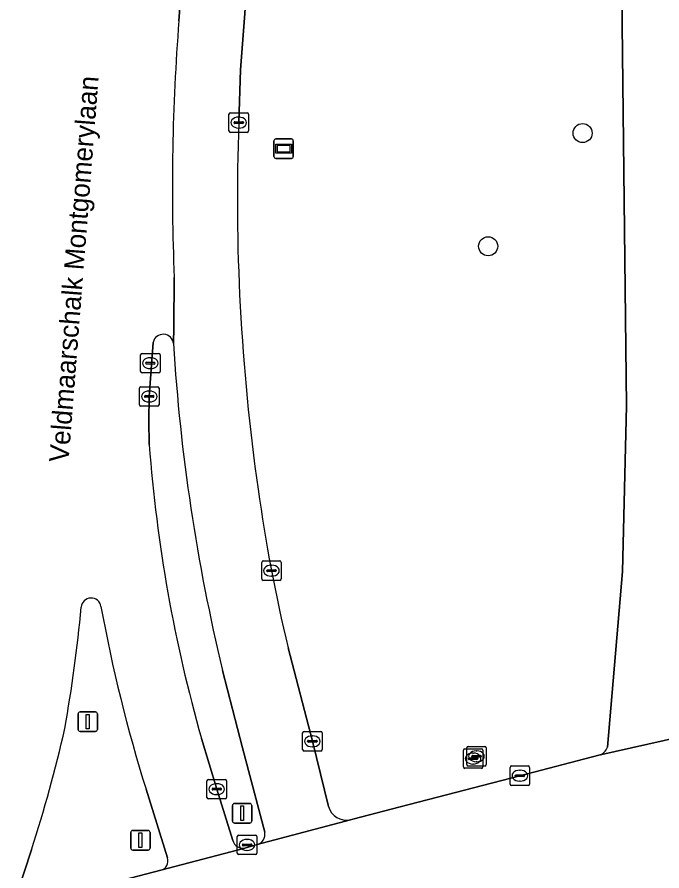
# Model space of a CAD drawing. Extents: x 160806 to 161707, y 383696 to 384148.
# Drawn here: x 161203.78 to 161236.82, y 383930.02 to 383973.77 of the extents above; entities that cross this region are included whole.
import ezdxf

# ---------------------------------------------------------------- set-up
doc = ezdxf.new("R2010")
doc.units = 0
for name, color, linetype in [('IMGEO_Berm_groen', 7, 'Continuous'), ('IMGEO_Boom', 7, 'Continuous'), ('IMGEO_Kolk', 7, 'Continuous'), ('IMGEO_Openbare_ruimte_label', 7, 'Continuous'), ('IMGEO_OVBaan_gesloten', 7, 'Continuous'), ('IMGEO_Rijbaan_lokaal_gesloten', 7, 'Continuous'), ('IMGEO_Rioolput', 7, 'Continuous'), ('IMGEO_Verkeerseiland_gesloten', 7, 'Continuous'), ('IMGEO_Verkeersregelinstallatiepaal', 7, 'Continuous'), ('IMGEO_Wegwijzer', 7, 'Continuous')]:
    doc.layers.add(name, color=color, linetype=linetype)

msp = doc.modelspace()

# ---------------------------------------------------------------- linework, layer by layer
at = {"layer": 'IMGEO_Berm_groen'}
for points in [[(161234.023, 383936.363), (161234.793, 383945.355), (161235.013, 383953.847), (161234.492, 383998.945), (161234.263, 384024.171)], [(161217.59, 384002.154), (161216.53, 383988.019), (161215.222, 383971.062), (161215.137, 383968.364)], [(161217.663, 383941.452), (161218.909, 383936.658), (161219.729, 383933.32)], [(161220.861, 383932.636), (161220.976, 383932.667), (161223.402, 383933.299), (161229.542, 383934.895), (161233.595, 383935.943)]]:
    msp.add_lwpolyline(points, dxfattribs=at)
for centre, radius, start, end in [((161320.498, 383964.509), 105.432, 177.9047, 188.14488), ((161299.612, 383961.128), 84.278, 187.88118, 193.50125), ((161233.438, 383936.531), 0.609, 284.9675, 343.9515), ((161220.669, 383933.597), 0.98, 196.3992, 281.3167)]:
    msp.add_arc(centre, radius, start, end, dxfattribs=at)
at = {"layer": 'IMGEO_Boom'}
for centre in [(161232.756, 383967.827), (161227.918, 383962.027)]:
    msp.add_circle(centre, 0.489, dxfattribs=at)
at = {"layer": 'IMGEO_Kolk'}
for p, q in [((161214.636, 383967.938), (161214.636, 383968.79)), ((161214.711, 383968.864), (161215.563, 383968.864)), ((161215.124, 383968.644), (161215.149, 383968.644)), ((161215.637, 383968.79), (161215.637, 383967.938)), ((161214.895, 383968.358), (161214.895, 383968.37)), ((161215.333, 383968.321), (161214.935, 383968.321)), ((161214.938, 383968.407), (161215.336, 383968.407)), ((161215.147, 383968.084), (161215.122, 383968.084)), ((161215.379, 383968.37), (161215.379, 383968.358)), ((161215.563, 383967.864), (161214.711, 383967.864)), ((161210.106, 383955.61), (161210.106, 383956.462)), ((161210.181, 383956.536), (161211.033, 383956.536)), ((161210.594, 383956.316), (161210.619, 383956.316)), ((161211.107, 383956.462), (161211.107, 383955.61)), ((161210.365, 383956.03), (161210.365, 383956.042)), ((161210.803, 383955.993), (161210.405, 383955.993)), ((161210.408, 383956.079), (161210.806, 383956.079)), ((161210.849, 383956.042), (161210.849, 383956.03)), ((161211.033, 383955.536), (161210.181, 383955.536)), ((161210.617, 383955.756), (161210.592, 383955.756)), ((161210.051, 383953.904), (161210.051, 383954.756)), ((161210.126, 383954.83), (161210.978, 383954.83)), ((161210.539, 383954.61), (161210.564, 383954.61)), ((161211.052, 383954.756), (161211.052, 383953.904)), ((161210.31, 383954.324), (161210.31, 383954.336)), ((161210.748, 383954.287), (161210.35, 383954.287)), ((161210.353, 383954.373), (161210.751, 383954.373)), ((161210.794, 383954.336), (161210.794, 383954.324)), ((161210.978, 383953.83), (161210.126, 383953.83)), ((161210.562, 383954.05), (161210.537, 383954.05)), ((161216.313, 383944.977), (161216.313, 383945.829)), ((161216.388, 383945.903), (161217.24, 383945.903)), ((161217.314, 383945.829), (161217.314, 383944.977)), ((161216.572, 383945.397), (161216.572, 383945.409)), ((161217.01, 383945.36), (161216.612, 383945.36)), ((161216.615, 383945.446), (161217.013, 383945.446)), ((161216.801, 383945.683), (161216.826, 383945.683)), ((161217.056, 383945.409), (161217.056, 383945.397)), ((161217.24, 383944.903), (161216.388, 383944.903)), ((161216.824, 383945.123), (161216.799, 383945.123)), ((161218.408, 383936.232), (161218.408, 383937.084)), ((161218.483, 383937.158), (161219.335, 383937.158)), ((161219.409, 383937.084), (161219.409, 383936.232)), ((161218.667, 383936.652), (161218.667, 383936.664)), ((161219.105, 383936.615), (161218.707, 383936.615)), ((161218.71, 383936.701), (161219.108, 383936.701)), ((161218.896, 383936.938), (161218.921, 383936.938)), ((161219.151, 383936.664), (161219.151, 383936.652)), ((161219.335, 383936.158), (161218.483, 383936.158)), ((161218.919, 383936.378), (161218.894, 383936.378)), ((161229.041, 383934.469), (161229.041, 383935.321)), ((161229.116, 383935.395), (161229.968, 383935.395)), ((161230.042, 383935.321), (161230.042, 383934.469)), ((161229.3, 383934.889), (161229.3, 383934.901)), ((161229.738, 383934.852), (161229.34, 383934.852)), ((161229.343, 383934.938), (161229.741, 383934.938)), ((161229.529, 383935.175), (161229.554, 383935.175)), ((161229.784, 383934.901), (161229.784, 383934.889)), ((161213.508, 383933.781), (161213.508, 383934.633)), ((161213.583, 383934.707), (161214.435, 383934.707)), ((161213.996, 383934.487), (161214.021, 383934.487)), ((161214.509, 383934.633), (161214.509, 383933.781)), ((161229.968, 383934.395), (161229.116, 383934.395)), ((161229.552, 383934.615), (161229.527, 383934.615)), ((161213.767, 383934.201), (161213.767, 383934.213)), ((161214.205, 383934.164), (161213.807, 383934.164)), ((161213.81, 383934.25), (161214.208, 383934.25)), ((161214.251, 383934.213), (161214.251, 383934.201)), ((161214.435, 383933.707), (161213.583, 383933.707)), ((161214.019, 383933.927), (161213.994, 383933.927)), ((161215.062, 383930.923), (161215.062, 383931.775)), ((161215.137, 383931.849), (161215.989, 383931.849)), ((161216.063, 383931.775), (161216.063, 383930.923)), ((161215.321, 383931.343), (161215.321, 383931.355)), ((161215.364, 383931.392), (161215.762, 383931.392)), ((161215.55, 383931.629), (161215.575, 383931.629)), ((161215.805, 383931.355), (161215.805, 383931.343)), ((161215.759, 383931.306), (161215.361, 383931.306)), ((161215.573, 383931.069), (161215.548, 383931.069)), ((161215.989, 383930.849), (161215.137, 383930.849))]:
    msp.add_line(p, q, dxfattribs=at)
for points in [[(161214.636, 383967.938), (161214.636, 383968.79)], [(161214.711, 383968.864), (161215.563, 383968.864)], [(161215.637, 383968.79), (161215.637, 383967.938)], [(161215.563, 383967.864), (161214.711, 383967.864)], [(161210.106, 383955.61), (161210.106, 383956.462)], [(161210.181, 383956.536), (161211.033, 383956.536)], [(161211.107, 383956.462), (161211.107, 383955.61)], [(161211.033, 383955.536), (161210.181, 383955.536)], [(161210.051, 383953.904), (161210.051, 383954.756)], [(161210.126, 383954.83), (161210.978, 383954.83)], [(161211.052, 383954.756), (161211.052, 383953.904)], [(161210.978, 383953.83), (161210.126, 383953.83)], [(161216.313, 383944.977), (161216.313, 383945.829)], [(161216.388, 383945.903), (161217.24, 383945.903)], [(161217.314, 383945.829), (161217.314, 383944.977)], [(161217.24, 383944.903), (161216.388, 383944.903)], [(161218.408, 383936.232), (161218.408, 383937.084)], [(161218.483, 383937.158), (161219.335, 383937.158)], [(161219.409, 383937.084), (161219.409, 383936.232)], [(161219.335, 383936.158), (161218.483, 383936.158)], [(161229.041, 383934.469), (161229.041, 383935.321)], [(161229.116, 383935.395), (161229.968, 383935.395)], [(161230.042, 383935.321), (161230.042, 383934.469)], [(161213.508, 383933.781), (161213.508, 383934.633)], [(161213.583, 383934.707), (161214.435, 383934.707)], [(161214.509, 383934.633), (161214.509, 383933.781)], [(161229.968, 383934.395), (161229.116, 383934.395)], [(161214.435, 383933.707), (161213.583, 383933.707)], [(161215.062, 383930.923), (161215.062, 383931.775)], [(161215.137, 383931.849), (161215.989, 383931.849)], [(161216.063, 383931.775), (161216.063, 383930.923)], [(161215.989, 383930.849), (161215.137, 383930.849)]]:
    msp.add_lwpolyline(points, dxfattribs=at)
for centre, radius, start, end in [((161214.713, 383968.788), 0.0765, 91.552, 178.448), ((161214.713, 383968.788), 0.0765, 91.552, 178.448), ((161215.561, 383968.788), 0.0765, 1.552, 88.448), ((161215.561, 383968.788), 0.0765, 1.552, 88.448), ((161214.935, 383968.367), 0.0403, 85.8775, 175.7526), ((161214.932, 383968.357), 0.0366, 178.938, 274.7102), ((161215.336, 383968.364), 0.043, 264.8664, 352.4533), ((161215.34, 383968.369), 0.0386, 1.7309, 96.639), ((161214.713, 383967.94), 0.0765, 181.552, 268.448), ((161214.713, 383967.94), 0.0765, 181.552, 268.448), ((161215.561, 383967.94), 0.0765, 271.552, 358.448), ((161215.561, 383967.94), 0.0765, 271.552, 358.448), ((161210.183, 383956.46), 0.0765, 91.552, 178.448), ((161210.183, 383956.46), 0.0765, 91.552, 178.448), ((161211.031, 383956.46), 0.0765, 1.552, 88.448), ((161211.031, 383956.46), 0.0765, 1.552, 88.448), ((161210.405, 383956.039), 0.0403, 85.8775, 175.7526), ((161210.402, 383956.029), 0.0366, 178.938, 274.7102), ((161210.806, 383956.036), 0.043, 264.8664, 352.4533), ((161210.81, 383956.041), 0.0386, 1.7309, 96.639), ((161210.183, 383955.612), 0.0765, 181.552, 268.448), ((161210.183, 383955.612), 0.0765, 181.552, 268.448), ((161211.031, 383955.612), 0.0765, 271.552, 358.448), ((161211.031, 383955.612), 0.0765, 271.552, 358.448), ((161210.128, 383954.754), 0.0765, 91.552, 178.448), ((161210.128, 383954.754), 0.0765, 91.552, 178.448), ((161210.976, 383954.754), 0.0765, 1.552, 88.448), ((161210.976, 383954.754), 0.0765, 1.552, 88.448), ((161210.35, 383954.333), 0.0403, 85.8775, 175.7526), ((161210.347, 383954.323), 0.0366, 178.938, 274.7102), ((161210.751, 383954.33), 0.043, 264.8664, 352.4533), ((161210.755, 383954.335), 0.0386, 1.7309, 96.639), ((161210.128, 383953.906), 0.0765, 181.552, 268.448), ((161210.128, 383953.906), 0.0765, 181.552, 268.448), ((161210.976, 383953.906), 0.0765, 271.552, 358.448), ((161210.976, 383953.906), 0.0765, 271.552, 358.448), ((161216.39, 383945.827), 0.0765, 91.552, 178.448), ((161216.39, 383945.827), 0.0765, 91.552, 178.448), ((161217.238, 383945.827), 0.0765, 1.552, 88.448), ((161217.238, 383945.827), 0.0765, 1.552, 88.448), ((161216.612, 383945.406), 0.0403, 85.8775, 175.7526), ((161216.609, 383945.396), 0.0366, 178.938, 274.7102), ((161217.013, 383945.403), 0.043, 264.8664, 352.4533), ((161217.017, 383945.408), 0.0386, 1.7309, 96.639), ((161216.39, 383944.979), 0.0765, 181.552, 268.448), ((161216.39, 383944.979), 0.0765, 181.552, 268.448), ((161217.238, 383944.979), 0.0765, 271.552, 358.448), ((161217.238, 383944.979), 0.0765, 271.552, 358.448), ((161218.485, 383937.082), 0.0765, 91.552, 178.448), ((161218.485, 383937.082), 0.0765, 91.552, 178.448), ((161219.333, 383937.082), 0.0765, 1.552, 88.448), ((161219.333, 383937.082), 0.0765, 1.552, 88.448), ((161218.707, 383936.661), 0.0403, 85.8775, 175.7526), ((161218.704, 383936.651), 0.0366, 178.938, 274.7102), ((161219.108, 383936.658), 0.043, 264.8664, 352.4533), ((161219.112, 383936.663), 0.0386, 1.7309, 96.639), ((161218.485, 383936.234), 0.0765, 181.552, 268.448), ((161218.485, 383936.234), 0.0765, 181.552, 268.448), ((161219.333, 383936.234), 0.0765, 271.552, 358.448), ((161219.333, 383936.234), 0.0765, 271.552, 358.448), ((161229.118, 383935.319), 0.0765, 91.552, 178.448), ((161229.118, 383935.319), 0.0765, 91.552, 178.448), ((161229.966, 383935.319), 0.0765, 1.552, 88.448), ((161229.966, 383935.319), 0.0765, 1.552, 88.448), ((161229.34, 383934.898), 0.0403, 85.8775, 175.7526), ((161229.337, 383934.888), 0.0366, 178.938, 274.7102), ((161229.741, 383934.895), 0.043, 264.8664, 352.4533), ((161229.745, 383934.9), 0.0386, 1.7309, 96.639), ((161213.585, 383934.631), 0.0765, 91.552, 178.448), ((161213.585, 383934.631), 0.0765, 91.552, 178.448), ((161214.433, 383934.631), 0.0765, 1.552, 88.448), ((161214.433, 383934.631), 0.0765, 1.552, 88.448), ((161229.118, 383934.471), 0.0765, 181.552, 268.448), ((161229.118, 383934.471), 0.0765, 181.552, 268.448), ((161229.966, 383934.471), 0.0765, 271.552, 358.448), ((161229.966, 383934.471), 0.0765, 271.552, 358.448), ((161213.807, 383934.21), 0.0403, 85.8775, 175.7526), ((161213.804, 383934.2), 0.0366, 178.938, 274.7102), ((161214.208, 383934.207), 0.043, 264.8664, 352.4533), ((161214.212, 383934.212), 0.0386, 1.7309, 96.639), ((161213.585, 383933.783), 0.0765, 181.552, 268.448), ((161213.585, 383933.783), 0.0765, 181.552, 268.448), ((161214.433, 383933.783), 0.0765, 271.552, 358.448), ((161214.433, 383933.783), 0.0765, 271.552, 358.448), ((161215.139, 383931.773), 0.0765, 91.552, 178.448), ((161215.139, 383931.773), 0.0765, 91.552, 178.448), ((161215.987, 383931.773), 0.0765, 1.552, 88.448), ((161215.987, 383931.773), 0.0765, 1.552, 88.448), ((161215.361, 383931.352), 0.0403, 85.8775, 175.7526), ((161215.358, 383931.342), 0.0366, 178.938, 274.7102), ((161215.762, 383931.349), 0.043, 264.8664, 352.4533), ((161215.766, 383931.354), 0.0386, 1.7309, 96.639), ((161215.139, 383930.925), 0.0765, 181.552, 268.448), ((161215.139, 383930.925), 0.0765, 181.552, 268.448), ((161215.987, 383930.925), 0.0765, 271.552, 358.448), ((161215.987, 383930.925), 0.0765, 271.552, 358.448)]:
    msp.add_arc(centre, radius, start, end, dxfattribs=at)
for centre, major_axis, ratio, start_param, end_param in [((161215.123, 383968.364), (-0.387, 0.002), 0.722429, 4.712389, 7.853982), ((161215.148, 383968.364), (-0.39, 0.002), 0.717154, 1.570796, 4.712389), ((161210.593, 383956.036), (-0.387, 0.002), 0.722429, 4.712389, 7.853982), ((161210.618, 383956.036), (-0.39, 0.002), 0.717154, 1.570796, 4.712389), ((161210.538, 383954.33), (-0.387, 0.002), 0.722429, 4.712389, 7.853982), ((161210.563, 383954.33), (-0.39, 0.002), 0.717154, 1.570796, 4.712389), ((161216.8, 383945.403), (-0.387, 0.002), 0.722429, 4.712389, 7.853982), ((161216.825, 383945.403), (-0.39, 0.002), 0.717154, 1.570796, 4.712389), ((161218.895, 383936.658), (-0.387, 0.002), 0.722429, 4.712389, 7.853982), ((161218.92, 383936.658), (-0.39, 0.002), 0.717154, 1.570796, 4.712389), ((161229.528, 383934.895), (-0.387, 0.002), 0.722429, 4.712389, 7.853982), ((161229.553, 383934.895), (-0.39, 0.002), 0.717154, 1.570796, 4.712389), ((161213.995, 383934.207), (-0.387, 0.002), 0.722429, 4.712389, 7.853982), ((161214.02, 383934.207), (-0.39, 0.002), 0.717154, 1.570796, 4.712389), ((161215.549, 383931.349), (-0.387, 0.002), 0.722429, 4.712389, 7.853982), ((161215.574, 383931.349), (-0.39, 0.002), 0.717154, 1.570796, 4.712389)]:
    msp.add_ellipse(centre, major_axis=major_axis, ratio=ratio, start_param=start_param, end_param=end_param, dxfattribs=at)
at = {"layer": 'IMGEO_OVBaan_gesloten'}
for points in [[(161214.441, 384004.323), (161212.071, 383973.586)], [(161215.137, 383968.364), (161215.222, 383971.062), (161216.53, 383988.019), (161217.59, 384002.154)], [(161211.83, 383960.427), (161211.811, 383957.889), (161211.793, 383957.036)], [(161219.729, 383933.32), (161218.909, 383936.658), (161217.663, 383941.452)], [(161214.31, 383940.287), (161215.337, 383936.331), (161216.466, 383931.999)], [(161216.084, 383931.37), (161220.861, 383932.636)]]:
    msp.add_lwpolyline(points, dxfattribs=at)
for centre, radius, start, end in [((161322.247, 383964.986), 110.511, 175.53696, 182.36459), ((161320.498, 383964.509), 105.432, 177.9047, 188.14488), ((161307.986, 383962.928), 96.373, 183.50511, 193.58753), ((161299.612, 383961.128), 84.278, 187.88118, 193.50125), ((161220.669, 383933.597), 0.98, 196.3992, 281.3167), ((161215.942, 383931.887), 0.536, 285.3781, 12.0801)]:
    msp.add_arc(centre, radius, start, end, dxfattribs=at)
at = {"layer": 'IMGEO_Rijbaan_lokaal_gesloten'}
for points in [[(161234.263, 384024.171), (161234.492, 383998.945), (161235.013, 383953.847), (161234.793, 383945.355), (161234.023, 383936.363)], [(161212.071, 383973.586), (161214.441, 384004.323)], [(161211.793, 383957.036), (161211.811, 383957.889), (161211.83, 383960.427)], [(161210.551, 383951.863), (161210.527, 383953.098), (161210.552, 383954.33), (161210.749, 383957.101)], [(161233.595, 383935.943), (161251.997, 383940.077), (161251.406, 383942.179)], [(161244.748, 383927.603), (161251.351, 383929.295), (161254.781, 383930.174), (161253.925, 383933.217), (161253.022, 383936.431), (161251.997, 383940.077), (161233.595, 383935.943), (161229.542, 383934.895), (161223.402, 383933.299), (161220.976, 383932.667), (161220.861, 383932.636), (161216.084, 383931.37), (161215.456, 383931.183), (161211.147, 383930.051), (161204.418, 383928.292)], [(161214.826, 383931.579), (161214.009, 383934.207), (161213.226, 383936.804)], [(161210.386, 383934.199), (161211.485, 383930.681)], [(161203.779, 383928.854), (161204.51, 383931.103)], [(161211.147, 383930.051), (161215.456, 383931.183)]]:
    msp.add_lwpolyline(points, dxfattribs=at)
for centre, radius, start, end in [((161322.247, 383964.986), 110.511, 175.53696, 182.36459), ((161211.266, 383956.986), 0.53, 5.4349, 167.4397), ((161286.07, 383957.511), 75.73, 184.27689, 195.86841), ((161207.572, 383943.487), 0.512, 9.1292, 174.7041), ((161132.556, 383950.401), 74.822, 349.92486, 354.73388), ((161286.065, 383957.811), 79.277, 190.34993, 197.32795), ((161140.112, 383952.221), 67.772, 341.84401, 347.29156), ((161233.438, 383936.531), 0.609, 284.9675, 343.9515), ((161215.357, 383931.724), 0.55, 195.3077, 280.3877), ((161211.017, 383930.527), 0.493, 285.3402, 18.232)]:
    msp.add_arc(centre, radius, start, end, dxfattribs=at)
at = {"layer": 'IMGEO_Rioolput'}
for p, q in [((161226.646, 383935.347), (161226.646, 383936.199)), ((161226.721, 383936.273), (161227.573, 383936.273)), ((161226.817, 383935.464), (161226.817, 383936.316)), ((161226.892, 383936.39), (161227.744, 383936.39)), ((161227.305, 383936.17), (161227.33, 383936.17)), ((161227.647, 383936.199), (161227.647, 383935.347)), ((161227.818, 383936.316), (161227.818, 383935.464)), ((161226.905, 383935.767), (161226.905, 383935.779)), ((161227.343, 383935.73), (161226.945, 383935.73)), ((161226.948, 383935.816), (161227.346, 383935.816)), ((161227.076, 383935.884), (161227.076, 383935.896)), ((161227.514, 383935.847), (161227.116, 383935.847)), ((161227.119, 383935.933), (161227.517, 383935.933)), ((161227.134, 383936.053), (161227.159, 383936.053)), ((161227.389, 383935.779), (161227.389, 383935.767)), ((161227.56, 383935.896), (161227.56, 383935.884)), ((161227.573, 383935.273), (161226.721, 383935.273)), ((161227.744, 383935.39), (161226.892, 383935.39)), ((161227.157, 383935.493), (161227.132, 383935.493)), ((161227.328, 383935.61), (161227.303, 383935.61))]:
    msp.add_line(p, q, dxfattribs=at)
for points in [[(161226.646, 383935.347), (161226.646, 383936.199)], [(161226.721, 383936.273), (161227.573, 383936.273)], [(161226.817, 383935.464), (161226.817, 383936.316)], [(161226.892, 383936.39), (161227.744, 383936.39)], [(161227.647, 383936.199), (161227.647, 383935.347)], [(161227.818, 383936.316), (161227.818, 383935.464)], [(161227.573, 383935.273), (161226.721, 383935.273)], [(161227.744, 383935.39), (161226.892, 383935.39)]]:
    msp.add_lwpolyline(points, dxfattribs=at)
for centre, radius, start, end in [((161226.723, 383936.197), 0.0765, 91.552, 178.448), ((161226.723, 383936.197), 0.0765, 91.552, 178.448), ((161226.894, 383936.314), 0.0765, 91.552, 178.448), ((161226.894, 383936.314), 0.0765, 91.552, 178.448), ((161227.571, 383936.197), 0.0765, 1.552, 88.448), ((161227.571, 383936.197), 0.0765, 1.552, 88.448), ((161227.742, 383936.314), 0.0765, 1.552, 88.448), ((161227.742, 383936.314), 0.0765, 1.552, 88.448), ((161226.945, 383935.776), 0.0403, 85.8775, 175.7526), ((161226.942, 383935.766), 0.0366, 178.938, 274.7102), ((161227.116, 383935.893), 0.0403, 85.8775, 175.7526), ((161227.113, 383935.883), 0.0366, 178.938, 274.7102), ((161227.346, 383935.773), 0.043, 264.8664, 352.4533), ((161227.35, 383935.778), 0.0386, 1.7309, 96.639), ((161227.517, 383935.89), 0.043, 264.8664, 352.4533), ((161227.521, 383935.895), 0.0386, 1.7309, 96.639), ((161226.723, 383935.349), 0.0765, 181.552, 268.448), ((161226.723, 383935.349), 0.0765, 181.552, 268.448), ((161226.894, 383935.466), 0.0765, 181.552, 268.448), ((161226.894, 383935.466), 0.0765, 181.552, 268.448), ((161227.571, 383935.349), 0.0765, 271.552, 358.448), ((161227.571, 383935.349), 0.0765, 271.552, 358.448), ((161227.742, 383935.466), 0.0765, 271.552, 358.448), ((161227.742, 383935.466), 0.0765, 271.552, 358.448)]:
    msp.add_arc(centre, radius, start, end, dxfattribs=at)
for centre, major_axis, ratio, start_param, end_param in [((161227.304, 383935.89), (-0.387, 0.002), 0.722429, 4.712389, 7.853982), ((161227.329, 383935.89), (-0.39, 0.002), 0.717154, 1.570796, 4.712389), ((161227.133, 383935.773), (-0.387, 0.002), 0.722429, 4.712389, 7.853982), ((161227.158, 383935.773), (-0.39, 0.002), 0.717154, 1.570796, 4.712389)]:
    msp.add_ellipse(centre, major_axis=major_axis, ratio=ratio, start_param=start_param, end_param=end_param, dxfattribs=at)
at = {"layer": 'IMGEO_Verkeerseiland_gesloten'}
for points in [[(161210.749, 383957.101), (161210.552, 383954.33), (161210.527, 383953.098), (161210.551, 383951.863)], [(161216.466, 383931.999), (161215.337, 383936.331), (161214.31, 383940.287)], [(161213.226, 383936.804), (161214.009, 383934.207), (161214.826, 383931.579)], [(161211.485, 383930.681), (161210.386, 383934.199)], [(161215.456, 383931.183), (161216.084, 383931.37)], [(161204.51, 383931.103), (161203.779, 383928.854)], [(161204.418, 383928.292), (161211.147, 383930.051)]]:
    msp.add_lwpolyline(points, dxfattribs=at)
for centre, radius, start, end in [((161211.266, 383956.986), 0.53, 5.4349, 167.4397), ((161307.986, 383962.928), 96.373, 183.50511, 193.58753), ((161286.07, 383957.511), 75.73, 184.27689, 195.86841), ((161207.572, 383943.487), 0.512, 9.1292, 174.7041), ((161132.556, 383950.401), 74.822, 349.92486, 354.73388), ((161286.065, 383957.811), 79.277, 190.34993, 197.32795), ((161140.112, 383952.221), 67.772, 341.84401, 347.29156), ((161215.942, 383931.887), 0.536, 285.3781, 12.0801), ((161215.357, 383931.724), 0.55, 195.3077, 280.3877), ((161211.017, 383930.527), 0.493, 285.3402, 18.232)]:
    msp.add_arc(centre, radius, start, end, dxfattribs=at)
at = {"layer": 'IMGEO_Verkeersregelinstallatiepaal'}
for p, q in [((161206.906, 383937.264), (161206.906, 383938.064)), ((161206.906, 383938.064), (161206.906, 383937.264)), ((161207.006, 383938.164), (161207.796, 383938.164)), ((161207.796, 383938.164), (161207.006, 383938.164)), ((161207.896, 383938.064), (161207.896, 383937.264)), ((161207.896, 383937.264), (161207.896, 383938.064)), ((161207.796, 383937.164), (161207.006, 383937.164)), ((161207.006, 383937.164), (161207.796, 383937.164)), ((161214.816, 383932.571), (161214.816, 383933.371)), ((161214.816, 383933.371), (161214.816, 383932.571)), ((161214.916, 383933.471), (161215.706, 383933.471)), ((161215.706, 383933.471), (161214.916, 383933.471)), ((161215.806, 383933.371), (161215.806, 383932.571)), ((161215.806, 383932.571), (161215.806, 383933.371)), ((161215.706, 383932.471), (161214.916, 383932.471)), ((161214.916, 383932.471), (161215.706, 383932.471)), ((161209.606, 383931.187), (161209.606, 383931.987)), ((161209.606, 383931.987), (161209.606, 383931.187)), ((161209.706, 383932.087), (161210.496, 383932.087)), ((161210.496, 383932.087), (161209.706, 383932.087)), ((161210.596, 383931.987), (161210.596, 383931.187)), ((161210.596, 383931.187), (161210.596, 383931.987)), ((161210.496, 383931.087), (161209.706, 383931.087)), ((161209.706, 383931.087), (161210.496, 383931.087))]:
    msp.add_line(p, q, dxfattribs=at)
for points in [[(161207.326, 383938.039), (161207.476, 383938.039), (161207.476, 383937.289), (161207.326, 383937.289), (161207.326, 383938.039)], [(161215.236, 383933.346), (161215.386, 383933.346), (161215.386, 383932.596), (161215.236, 383932.596), (161215.236, 383933.346)], [(161210.026, 383931.962), (161210.176, 383931.962), (161210.176, 383931.212), (161210.026, 383931.212), (161210.026, 383931.962)]]:
    msp.add_lwpolyline(points, dxfattribs=at)
for centre, start, end in [((161207.006, 383938.064), 90, 180), ((161207.006, 383938.064), 90, 180), ((161207.796, 383938.064), 0, 90), ((161207.796, 383938.064), 360, 90), ((161207.006, 383937.264), 180, 270), ((161207.006, 383937.264), 180, 270), ((161207.796, 383937.264), 270, 0), ((161207.796, 383937.264), 270, 0), ((161214.916, 383933.371), 90, 180), ((161214.916, 383933.371), 90, 180), ((161215.706, 383933.371), 0, 90), ((161215.706, 383933.371), 360, 90), ((161214.916, 383932.571), 180, 270), ((161214.916, 383932.571), 180, 270), ((161215.706, 383932.571), 270, 0), ((161215.706, 383932.571), 270, 0), ((161209.706, 383931.987), 90, 180), ((161209.706, 383931.987), 90, 180), ((161210.496, 383931.987), 0, 90), ((161210.496, 383931.987), 360, 90), ((161209.706, 383931.187), 180, 270), ((161209.706, 383931.187), 180, 270), ((161210.496, 383931.187), 270, 0), ((161210.496, 383931.187), 270, 0)]:
    msp.add_arc(centre, 0.1, start, end, dxfattribs=at)
at = {"layer": 'IMGEO_Wegwijzer'}
for p, q in [((161216.943, 383966.631), (161216.943, 383967.431)), ((161216.943, 383967.431), (161216.943, 383966.631)), ((161217.043, 383967.531), (161217.833, 383967.531)), ((161217.833, 383967.531), (161217.043, 383967.531)), ((161217.933, 383967.431), (161217.933, 383966.631)), ((161217.933, 383966.631), (161217.933, 383967.431)), ((161217.833, 383966.531), (161217.043, 383966.531)), ((161217.043, 383966.531), (161217.833, 383966.531))]:
    msp.add_line(p, q, dxfattribs=at)
for points in [[(161217.044, 383967.263), (161217.832, 383967.263), (161217.832, 383966.799), (161217.044, 383966.799), (161217.044, 383967.263)], [(161217.109, 383967.198), (161217.109, 383966.864), (161217.767, 383966.864), (161217.767, 383967.198), (161217.109, 383967.198)]]:
    msp.add_lwpolyline(points, dxfattribs=at)
for centre, start, end in [((161217.043, 383967.431), 90, 180), ((161217.043, 383967.431), 90, 180), ((161217.833, 383967.431), 0, 90), ((161217.833, 383967.431), 360, 90), ((161217.043, 383966.631), 180, 270), ((161217.043, 383966.631), 180, 270), ((161217.833, 383966.631), 270, 0), ((161217.833, 383966.631), 270, 0)]:
    msp.add_arc(centre, 0.1, start, end, dxfattribs=at)

# ---------------------------------------------------------------- texts
at = {"layer": 'IMGEO_Openbare_ruimte_label'}
msp.add_text('Veldmaarschalk Montgomerylaan', height=1, rotation=85.5266, dxfattribs=at).set_placement((161206.413, 383950.928))

doc.saveas('drawing.dxf')
